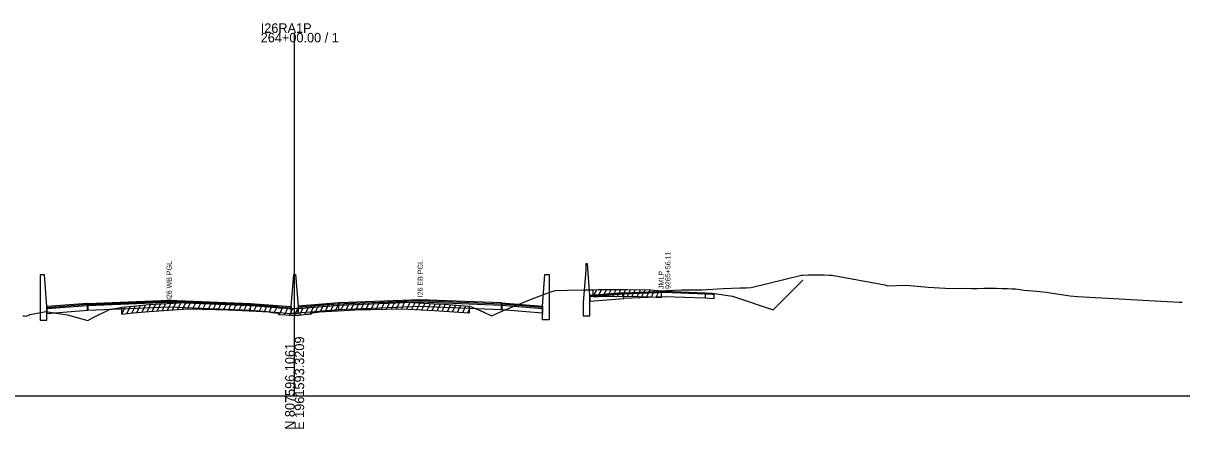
# Model space of a CAD drawing. Extents: x 1017 to 19997, y -1947 to 50737.
# Drawn here: x 10520 to 10861.4, y 13990.3 to 14109.7 of the extents above; entities that cross this region are included whole.
import ezdxf

# ---------------------------------------------------------------- set-up
doc = ezdxf.new("R2010")
doc.units = 0
for name, color, linetype in [('RD_GPK_XS_Cell', 7, 'Continuous'), ('RD_XS_Base', 7, 'Continuous'), ('RD_XS_ExGround', 7, 'Continuous'), ('RD_XS_ExPaveRet', 7, 'Continuous'), ('RD_XS_Greenside', 7, 'Continuous'), ('RD_XS_MedBWall', 7, 'Continuous'), ('RD_XS_Pave', 7, 'Continuous'), ('RD_XS_PaveOvlay', 7, 'Continuous'), ('RD_XS_TieSlope', 7, 'Continuous'), ('RD_XS_TX_Notes', 7, 'Continuous')]:
    doc.layers.add(name, color=color, linetype=linetype)

msp = doc.modelspace()

# ---------------------------------------------------------------- linework, layer by layer
at = {"layer": 'RD_GPK_XS_Cell'}
for p, q in [((10600, 14000), (10600, 14106.88)), ((10000, 14000), (10600, 14000)), ((10600, 14000), (11200, 14000))]:
    msp.add_line(p, q, dxfattribs=at)
at = {"layer": 'RD_XS_Base'}
for points in [[(10697, 14030.05), (10687, 14029.25)], [(10687, 14029.25), (10687, 14027.92)], [(10697, 14030.05), (10709, 14030.53), (10721, 14030.05)], [(10697, 14028.72), (10697, 14030.05)], [(10721, 14028.74), (10709, 14029.2), (10697, 14028.72)], [(10721, 14030.05), (10721, 14028.74)], [(10721, 14030.05), (10723, 14029.97), (10723.5, 14029.95)], [(10723.5, 14029.95), (10723.5, 14028.62)], [(10539, 14026.55), (10527, 14025.59)], [(10527, 14025.59), (10527, 14024.25)], [(10539, 14025.21), (10539, 14026.55)], [(10539.05, 14026.55), (10539.05, 14025.21)], [(10539.05, 14025.21), (10563, 14026.18), (10587, 14025.21)], [(10587, 14025.21), (10587, 14026.55)], [(10599, 14025.61), (10587, 14026.55)], [(10599, 14024.27), (10599, 14025.61)], [(10601, 14024.4), (10601, 14025.74)], [(10613, 14025.35), (10613, 14026.69)], [(10660.95, 14025.35), (10637, 14026.31), (10613, 14025.35)], [(10660.95, 14025.35), (10660.95, 14026.69)], [(10661, 14026.68), (10661, 14025.34)], [(10661, 14026.68), (10673, 14025.72)], [(10661, 14025.34), (10661, 14026.68)], [(10673, 14025.72), (10673, 14024.38)], [(10687, 14027.92), (10697, 14028.72)], [(10723.5, 14028.62), (10721, 14028.74)], [(10527, 14024.25), (10539, 14025.21)], [(10539.05, 14025.21), (10539, 14025.21)], [(10587, 14025.21), (10599, 14024.27)], [(10613, 14025.35), (10601, 14024.4)], [(10661, 14025.34), (10660.95, 14025.35)], [(10673, 14024.38), (10661, 14025.34)]]:
    msp.add_lwpolyline(points, dxfattribs=at)
at = {"layer": 'RD_XS_ExGround'}
msp.add_lwpolyline([(10519.92, 14023.57), (10520.39, 14023.57), (10520.92, 14023.49), (10522.04, 14023.98), (10526.68, 14024.88), (10532.99, 14023.91), (10539.05, 14022.21), (10540.38, 14022.97), (10545.63, 14025.51), (10548.25, 14025.89), (10549.04, 14026.09), (10552.38, 14026.41), (10557.16, 14026.87), (10564.2, 14027.34), (10568.61, 14027.63), (10572.7, 14027.51), (10580.47, 14027.3), (10588.63, 14026.9), (10592.37, 14026.73), (10593.31, 14026.58), (10595.15, 14026.34), (10595.26, 14025.94), (10597.44, 14025.82), (10598.41, 14025.75), (10600, 14025.77), (10600.39, 14025.78), (10601.24, 14025.81), (10603.47, 14026.01), (10604.32, 14026.06), (10605.01, 14026.19), (10605.15, 14026.47), (10606.72, 14026.67), (10607.35, 14026.76), (10616.38, 14027.25), (10619.42, 14027.43), (10622.59, 14027.48), (10631.49, 14027.67), (10641.25, 14027.15), (10644.04, 14026.99), (10649.97, 14026.56), (10651.52, 14026.45), (10652.79, 14025.89), (10655.5, 14024.74), (10658.04, 14023.56), (10661.5, 14025.09), (10669.49, 14028.39), (10674.43, 14030.24), (10676.75, 14031), (10680.35, 14031.11), (10685.28, 14031.2), (10687.98, 14031.24), (10689.46, 14031.29), (10697.93, 14031.37), (10704.87, 14031.19), (10708.05, 14030.96), (10708.79, 14030.97), (10709.55, 14031.04), (10714.13, 14031.19), (10720.1, 14031.21), (10726.31, 14031.59), (10731.25, 14031.86), (10731.75, 14031.82), (10732.24, 14031.79), (10733, 14031.78), (10734.47, 14031.91), (10749.35, 14035.58), (10749.67, 14035.58), (10751.36, 14035.61), (10753.12, 14035.62), (10755, 14035.61), (10756.07, 14035.63), (10757.54, 14035.58), (10758.19, 14035.54), (10758.89, 14035.41), (10773.9, 14032.65), (10774.63, 14032.44), (10780.2, 14032.55), (10786.68, 14032.02), (10793.38, 14031.62), (10798.03, 14031.68), (10799.4, 14031.57), (10801.14, 14031.62), (10803.12, 14031.75), (10804.98, 14031.75), (10806.67, 14031.68), (10808.47, 14031.6), (10810.02, 14031.57), (10811.41, 14031.55), (10812.4, 14031.51), (10814.96, 14031.17), (10818.71, 14030.85), (10821.47, 14030.51), (10822.67, 14030.31), (10828.54, 14029.48), (10830.69, 14029.27), (10860.67, 14027.62), (10861.55, 14027.56)], dxfattribs=at)
at = {"layer": 'RD_XS_ExPaveRet'}
for p, q in [((10687.98, 14029.24), (10689, 14031.27)), ((10687.98, 14029.24), (10687.98, 14031.24)), ((10689.43, 14029.29), (10690.44, 14031.3)), ((10690.86, 14029.3), (10691.87, 14031.31)), ((10692.3, 14029.32), (10693.3, 14031.33)), ((10693.73, 14029.33), (10694.73, 14031.34)), ((10695.16, 14029.35), (10696.16, 14031.36)), ((10696.6, 14029.36), (10697.6, 14031.37)), ((10698.04, 14029.37), (10699.03, 14031.34)), ((10699.47, 14029.33), (10700.45, 14031.31)), ((10700.89, 14029.29), (10701.88, 14031.27)), ((10702.31, 14029.26), (10703.3, 14031.23)), ((10703.73, 14029.22), (10704.72, 14031.19)), ((10705.15, 14029.17), (10706.12, 14031.1)), ((10706.55, 14029.07), (10707.51, 14031)), ((10708.01, 14028.96), (10708.05, 14029.04)), ((10708.05, 14028.96), (10708.05, 14030.96)), ((10549.04, 14024.09), (10550.09, 14026.19)), ((10549.04, 14024.09), (10549.04, 14026.09)), ((10550.54, 14024.23), (10551.59, 14026.34)), ((10552.04, 14024.38), (10553.09, 14026.48)), ((10553.53, 14024.53), (10554.58, 14026.63)), ((10555.03, 14024.67), (10556.08, 14026.77)), ((10556.52, 14024.81), (10557.57, 14026.9)), ((10558.02, 14024.93), (10559.05, 14027)), ((10559.51, 14025.03), (10560.54, 14027.1)), ((10561, 14025.13), (10562.03, 14027.2)), ((10562.49, 14025.23), (10563.53, 14027.3)), ((10563.98, 14025.33), (10565.02, 14027.4)), ((10565.47, 14025.43), (10566.51, 14027.5)), ((10566.97, 14025.53), (10568, 14027.59)), ((10568.46, 14025.62), (10569.45, 14027.61)), ((10569.96, 14025.59), (10570.95, 14027.57)), ((10571.47, 14025.55), (10572.45, 14027.52)), ((10572.98, 14025.51), (10573.96, 14027.48)), ((10574.48, 14025.47), (10575.47, 14027.44)), ((10575.99, 14025.42), (10576.98, 14027.4)), ((10577.5, 14025.38), (10578.49, 14027.36)), ((10579.01, 14025.34), (10579.99, 14027.32)), ((10580.52, 14025.3), (10581.49, 14027.25)), ((10582.01, 14025.23), (10582.99, 14027.18)), ((10583.51, 14025.15), (10584.49, 14027.1)), ((10585.01, 14025.08), (10585.99, 14027.03)), ((10586.51, 14025), (10587.48, 14026.96)), ((10588.01, 14024.93), (10588.98, 14026.88)), ((10589.51, 14024.86), (10590.48, 14026.81)), ((10591.01, 14024.79), (10591.98, 14026.75)), ((10592.5, 14024.71), (10593.43, 14026.57)), ((10593.99, 14024.49), (10594.93, 14026.37)), ((10595.47, 14023.92), (10596.45, 14025.87)), ((10596.98, 14023.85), (10597.94, 14025.78)), ((10598.47, 14023.75), (10599.48, 14025.76)), ((10599.97, 14023.77), (10600.99, 14025.8)), ((10601.49, 14023.83), (10602.54, 14025.93)), ((10603.01, 14023.97), (10604.05, 14026.04)), ((10604.52, 14024.1), (10605.74, 14026.55)), ((10606.02, 14024.58), (10607.09, 14026.72)), ((10607.52, 14024.77), (10608.55, 14026.82)), ((10609.02, 14024.85), (10610.05, 14026.91)), ((10610.53, 14024.93), (10611.55, 14026.99)), ((10612.03, 14025.01), (10613.05, 14027.07)), ((10613.53, 14025.1), (10614.56, 14027.15)), ((10615.03, 14025.18), (10616.06, 14027.24)), ((10616.53, 14025.26), (10617.56, 14027.32)), ((10618.03, 14025.35), (10619.06, 14027.4)), ((10619.53, 14025.43), (10620.54, 14027.45)), ((10621.02, 14025.46), (10622.03, 14027.47)), ((10622.52, 14025.48), (10623.53, 14027.5)), ((10624.02, 14025.51), (10625.03, 14027.53)), ((10625.52, 14025.54), (10626.53, 14027.57)), ((10627.02, 14025.58), (10628.03, 14027.6)), ((10628.52, 14025.61), (10629.53, 14027.63)), ((10630.02, 14025.64), (10631.03, 14027.66)), ((10631.52, 14025.67), (10632.49, 14027.61)), ((10633.01, 14025.59), (10633.99, 14027.54)), ((10634.51, 14025.51), (10635.49, 14027.46)), ((10636.01, 14025.43), (10636.99, 14027.38)), ((10637.51, 14025.35), (10638.49, 14027.3)), ((10639.01, 14025.27), (10639.99, 14027.22)), ((10640.51, 14025.19), (10641.49, 14027.14)), ((10642.01, 14025.11), (10642.98, 14027.05)), ((10643.5, 14025.02), (10644.47, 14026.96)), ((10645, 14024.92), (10645.97, 14026.85)), ((10646.5, 14024.81), (10647.47, 14026.74)), ((10648, 14024.7), (10648.97, 14026.63)), ((10649.51, 14024.59), (10650.48, 14026.52)), ((10651.52, 14024.45), (10651.52, 14026.45)), ((10651.02, 14024.49), (10651.52, 14025.49))]:
    msp.add_line(p, q, dxfattribs=at)
for points in [[(10687.98, 14029.24), (10689.46, 14029.29), (10697.93, 14029.37), (10704.87, 14029.19), (10708.05, 14028.96)], [(10549.04, 14024.09), (10552.38, 14024.41), (10557.16, 14024.87), (10564.2, 14025.34), (10568.61, 14025.63), (10572.7, 14025.51), (10580.47, 14025.3), (10588.63, 14024.9), (10592.37, 14024.73), (10593.31, 14024.58), (10595.15, 14024.34), (10595.26, 14023.94), (10597.44, 14023.82), (10598.41, 14023.75), (10600, 14023.77), (10600.39, 14023.78), (10601.24, 14023.81), (10603.47, 14024.01), (10604.32, 14024.06), (10605.01, 14024.19), (10605.15, 14024.47), (10606.72, 14024.67), (10607.35, 14024.76), (10616.38, 14025.25), (10619.42, 14025.43), (10622.59, 14025.48), (10631.49, 14025.67), (10641.25, 14025.15), (10644.04, 14024.99), (10649.97, 14024.56), (10651.52, 14024.45)]]:
    msp.add_lwpolyline(points, dxfattribs=at)
at = {"layer": 'RD_XS_Greenside'}
for points in [[(10723, 14030.29), (10729, 14029.33)], [(10729, 14029.33), (10741, 14025.33)]]:
    msp.add_lwpolyline(points, dxfattribs=at)
at = {"layer": 'RD_XS_MedBWall'}
for points in [[(10685.75, 14036.91), (10685, 14027.57)], [(10687, 14029.57), (10686.25, 14038.91), (10685.75, 14038.91)], [(10685.75, 14038.91), (10685.75, 14036.91)], [(10527, 14026.27), (10526.25, 14035.61), (10525, 14035.61)], [(10525, 14035.61), (10525, 14022.27)], [(10599, 14026.27), (10599.75, 14035.74), (10600.25, 14035.74), (10601, 14026.4)], [(10673, 14026.4), (10673.75, 14035.74), (10675, 14035.74)], [(10675, 14035.74), (10675, 14022.4)], [(10687, 14023.57), (10687, 14029.57)], [(10527, 14022.27), (10527, 14026.27)], [(10599, 14024.27), (10599, 14026.27)], [(10601, 14026.4), (10601, 14024.27)], [(10673, 14022.4), (10673, 14026.4)], [(10685, 14027.57), (10685, 14023.57)], [(10525, 14022.27), (10527, 14022.27)], [(10601, 14024.27), (10599, 14024.27)], [(10675, 14022.4), (10673, 14022.4)], [(10685, 14023.57), (10687, 14023.57)]]:
    msp.add_lwpolyline(points, dxfattribs=at)
at = {"layer": 'RD_XS_Pave'}
for points in [[(10539, 14026.89), (10527, 14025.93)], [(10527, 14025.93), (10527, 14025.59)], [(10539, 14026.55), (10539, 14026.89)], [(10539.05, 14026.55), (10539, 14026.55)], [(10539.05, 14026.89), (10563, 14027.85), (10587, 14026.89)], [(10587, 14026.55), (10563, 14027.52), (10539.05, 14026.55)], [(10539.05, 14026.55), (10539.05, 14026.89)], [(10587, 14026.89), (10587, 14026.55)], [(10587, 14026.89), (10599, 14025.95)], [(10599, 14025.95), (10599, 14025.61)], [(10613, 14027.03), (10601, 14026.08)], [(10601, 14025.74), (10613, 14026.69)], [(10601, 14026.08), (10601, 14025.74)], [(10660.95, 14027.03), (10637, 14027.99), (10613, 14027.03)], [(10613, 14026.69), (10637, 14027.65), (10660.95, 14026.69)], [(10613, 14027.03), (10613, 14026.69)], [(10660.95, 14026.69), (10660.95, 14027.03)], [(10660.95, 14027.03), (10661, 14027.02)], [(10661, 14026.68), (10660.95, 14026.69)], [(10661, 14027.02), (10661, 14026.68)], [(10661, 14026.68), (10661, 14027.02)], [(10673, 14026.06), (10673, 14025.72)]]:
    msp.add_lwpolyline(points, dxfattribs=at)
at = {"layer": 'RD_XS_PaveOvlay'}
for points in [[(10697, 14030.37), (10687, 14029.57)], [(10687, 14029.25), (10697, 14030.05)], [(10687, 14029.57), (10687, 14029.25)], [(10697, 14030.37), (10709, 14030.85), (10721, 14030.37)], [(10721, 14030.05), (10709, 14030.53), (10697, 14030.05)], [(10697, 14030.05), (10697, 14030.37)], [(10721, 14030.37), (10721, 14030.05)], [(10721, 14030.37), (10723, 14030.29)], [(10723, 14029.97), (10721, 14030.05)], [(10723, 14030.29), (10723, 14029.97)], [(10539, 14027.23), (10527, 14026.27)], [(10527, 14026.27), (10527, 14025.93)], [(10539.05, 14027.23), (10539, 14027.23)], [(10539, 14027.23), (10539, 14026.89)], [(10539, 14026.89), (10539.05, 14026.89)], [(10539.05, 14027.23), (10563, 14028.19), (10587, 14027.23)], [(10539.05, 14026.89), (10539.05, 14027.23)], [(10587, 14027.23), (10587, 14026.89)], [(10587, 14027.23), (10599, 14026.27)], [(10599, 14026.27), (10599, 14025.95)], [(10613, 14027.36), (10601, 14026.4)], [(10601, 14026.4), (10601, 14026.08)], [(10660.95, 14027.36), (10637, 14028.32), (10613, 14027.36)], [(10613, 14027.36), (10613, 14027.03)], [(10660.95, 14027.03), (10660.95, 14027.36)], [(10660.95, 14027.36), (10661, 14027.36)], [(10661, 14027.36), (10661, 14027.02)], [(10661, 14027.36), (10673, 14026.4)], [(10661, 14027.02), (10661, 14027.36)], [(10673, 14026.06), (10661, 14027.02)], [(10673, 14026.4), (10673, 14026.06)]]:
    msp.add_lwpolyline(points, dxfattribs=at)
at = {"layer": 'RD_XS_TieSlope'}
msp.add_lwpolyline([(10741, 14025.33), (10749.78, 14034.11)], dxfattribs=at)

# ---------------------------------------------------------------- texts
at = {"layer": 'RD_GPK_XS_Cell'}
for s, p in [('I26RA1P', (10590, 14106.88)), ('264+00.00 / 1', (10590, 14104.08))]:
    msp.add_text(s, height=2.8, dxfattribs=at).set_placement(p)
for s, p in [('N 807596.1061', (10600, 13990)), ('E 1961593.3209', (10602.8, 13990))]:
    msp.add_text(s, height=2.8, rotation=90, dxfattribs=at).set_placement(p)
at = {"layer": 'RD_XS_TX_Notes'}
for s, p in [('I26 WB PGL', (10563.75, 14028.19)), ('I26 EB PGL', (10637.75, 14029.05)), (' 9265+56.11', (10710.73, 14030.9)), (' JMLP', (10708.77, 14030.9))]:
    msp.add_text(s, height=1.5, rotation=90, dxfattribs=at).set_placement(p)

doc.saveas('drawing.dxf')
